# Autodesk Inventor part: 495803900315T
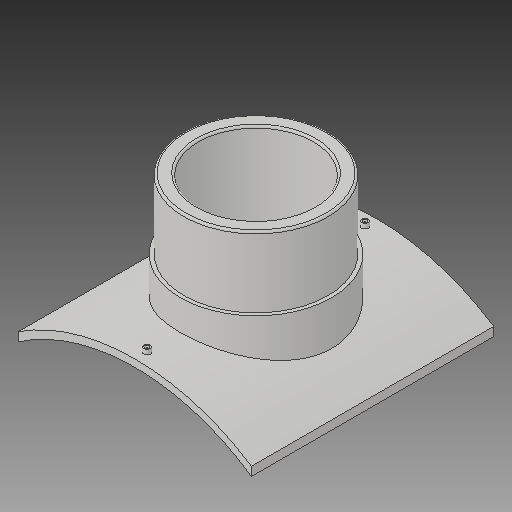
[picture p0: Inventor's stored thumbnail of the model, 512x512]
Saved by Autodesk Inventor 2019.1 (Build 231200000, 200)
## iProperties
Created: 2017-10
Part Number: 495803900315T
Material: Generic
Description: PLASSON BRANCH SADDLE  900x315
Document SubType Name: Modeling
Designer: KIM
Mass: 2754.05 g
Surface Area: 3037.44 cm^2
Volume: 2754.05 cm^3
Density: 1 g/cm^3
Appearance: Default
Author: KIM
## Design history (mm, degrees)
derived "495803.ipt"
feature "Solid1::495803.ipt"
tag "TaggingFeature1"
body "Solid1"
other parameters: "d1" = 16, "d4" = 0, "d12" = 475.6, "d13" = 14, "d14" = 238.5, "d16" = 5 deg, "d18" = 4, "d19" = 14, "d20" = 0, "d21" = 3, "d22" = 0, "d23" = 686, "d24" = 330.75, "d25" = 16, "d26" = 252, "d28" = 0, "d29" = 9.6, "d31" = 0, "d33" = 0, "d34" = 9, "d36" = 315, "d37" = 154, "d38" = 0, "d39" = 4.5, "d_1" = 315, "x_" = 16, "D_" = 16
